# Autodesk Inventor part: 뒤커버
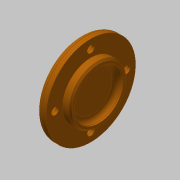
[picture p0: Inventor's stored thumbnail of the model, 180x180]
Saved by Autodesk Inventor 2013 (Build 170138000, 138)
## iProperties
Created: 2019-06
Part Number: 뒤커버
Material: 알루미늄 6061
Document SubType Name: Modeling
Designer: mduedu
Density: 2.71 g/cm^3
Mass: 40.7816 g
Surface Area: 66.9584 cm^2
Volume: 15.0486 cm^3
Author: mduedu
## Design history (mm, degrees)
sketch "스케치1"
  geometry: L1 (0, 0)-(-5, 0); L2 (-5, 0)-(-5, 17.5); L3 (-5, 17.5)-(0, 17.5); L4 (0, 17.5)-(0, 0); L5 (-5, 0)-(-11, 0); L6 (-11, 0)-(-11, 27.5); L7 (-11, 27.5)-(-5, 27.5); L8 (-5, 27.5)-(-5, 0)
  constraints: 16 end point, 4 parallel, 2 horizontal, 2 perpendicular
  dimensions: "d0" = 11 distance between parallel lines of L4 L6; "d2" = 5 distance of L2.end L3.end; "d3" = 55 diameter of L7 L5; "d4" = 35 diameter of L3 L1
revolve "회전1" sketch "스케치1" stored, may be unused: angle "d5" = 90 deg
sketch "스케치2"
  geometry: C1 r 15 at (0, 0); 1 further point
  constraints: 1 centre point, 1 coincident
  dimensions: "d6" = 30 diameter of C1
extrude "돌출1" cut sketch "스케치2" distance "d7" = 4; taper "d8" = 0 deg
fillet "모깎기1" dims "d9" = 3
fillet "모깎기2" dims "d10" = 3
chamfer "모따기1" distance "d11" = 1; stored, may be unused: second distance "d12" = 2, angle "d13" = 45 deg
sketch "스케치3" dims "d14" = 44
  geometry: 3 further points
  constraints: 2 vertical alignment, 1 coincident, 2 other
hole "구멍1" sketch "스케치3" at (0, 22) diameter "d15" = 4.5; stored, may be unused: countersink angle "d19" = 90 deg, drill point angle "d21" = 118 deg; dims "d16" = 6, "d17" = 8, "d18" = 4.4, "d20" = 8
node "솔리드1"
pattern_circular "원형 패턴1" dims angle "d23" = 360 deg
